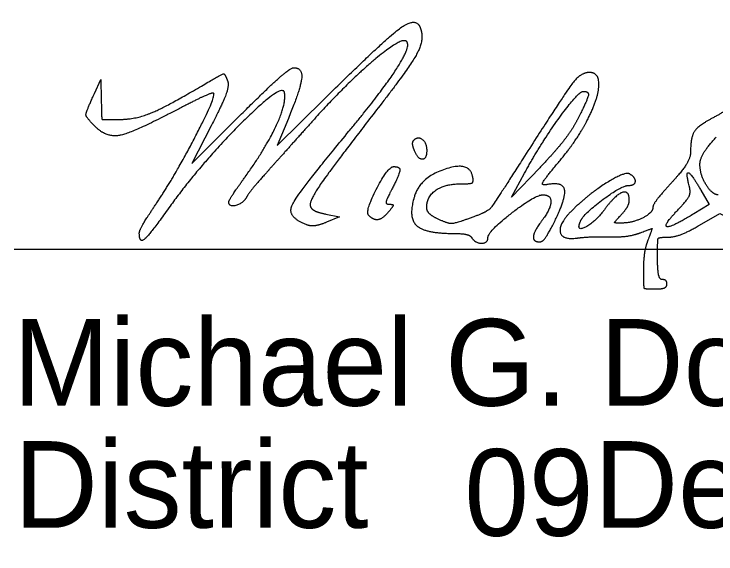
# Model space of a CAD drawing. Extents: x 0 to 40.2, y 0 to 22.
# Drawn here: x 24.5 to 25.632, y 8.324 to 9.196 of the extents above; entities that cross this region are included whole.
import ezdxf

# ---------------------------------------------------------------- set-up
doc = ezdxf.new("R2010")
doc.units = 0
doc.layers.add('SH_Data', color=7, linetype='Continuous')
doc.layers.add('SH_Text', color=7, linetype='Continuous')

msp = doc.modelspace()

# ---------------------------------------------------------------- linework, layer by layer
at = {"layer": 'SH_Data'}
msp.add_line((24.5, 8.816), (28, 8.816), dxfattribs=at)
at = {"layer": 'SH_Text'}
for p, q in [((25.1455, 8.9761), (25.1455, 8.9761)), ((25.0723, 8.8703), (25.0723, 8.8703)), ((24.7021, 8.842), (24.7021, 8.842))]:
    msp.add_line(p, q, dxfattribs=at)
for points in [[(24.6296, 9.067), (24.6401, 9.0898), (24.6407, 9.0575)], [(24.9425, 9.0269), (24.9245, 8.9834), (25.0015, 9.0594)], [(24.818, 9.015), (24.7867, 8.9543), (24.8642, 9.0315)], [(25.3481, 8.9474), (25.3027, 8.8998), (25.3235, 8.9384)], [(25.6082, 8.9109), (25.6213, 8.8879), (25.5968, 8.873)], [(25.0029, 8.8725), (25.0251, 8.868), (25.0043, 8.8594)], [(25.6056, 8.8544), (25.6388, 8.8734), (25.6847, 8.8505)]]:
    msp.add_lwpolyline(points, dxfattribs=at)
for points in [[(25.7902, 9.1956), (25.7938, 9.1838), (25.6607, 9.0449), (25.6314, 9.03)], [(25.0015, 9.0594), (25.0959, 9.1527), (25.1484, 9.1916), (25.1553, 9.1735)], [(25.1553, 9.1735), (25.1622, 9.1555), (25.1402, 9.1122), (25.0934, 9.0518)], [(25.1333, 9.1513), (25.1255, 9.1591), (25.0346, 9.082), (24.9821, 9.0233)], [(25.0402, 9.0062), (25.0944, 9.0716), (25.1407, 9.1439), (25.1333, 9.1513)], [(24.8642, 9.0315), (24.9069, 9.074), (24.946, 9.1088), (24.9511, 9.1088)], [(24.9511, 9.1088), (24.9658, 9.1088), (24.9622, 9.0746), (24.9425, 9.0269)], [(24.8022, 9.0792), (24.8352, 9.0986), (24.84, 9.0996), (24.8443, 9.0883)], [(25.4283, 9.1012), (25.4143, 9.1012), (25.3884, 9.0676), (25.3207, 8.9615)], [(25.4233, 9.0213), (25.4421, 9.0569), (25.4448, 9.1012), (25.4283, 9.1012)], [(24.8443, 9.0883), (24.8473, 9.0806), (24.8369, 9.0517), (24.818, 9.015)], [(24.6669, 9.0252), (24.6948, 9.0252), (24.7439, 9.0448), (24.8022, 9.0792)], [(24.9363, 9.0688), (24.933, 9.0855), (24.7994, 8.9521), (24.7499, 8.8827)], [(25.3235, 8.9384), (25.3479, 8.9838), (25.4102, 9.0706), (25.4184, 9.0707)], [(25.4184, 9.0707), (25.4279, 9.0708), (25.4249, 9.0565), (25.4088, 9.025)], [(24.6312, 9.0136), (24.6161, 9.0287), (24.6158, 9.0368), (24.6296, 9.067)], [(24.7295, 8.8895), (24.7593, 8.9337), (24.8264, 9.063), (24.8218, 9.0676)], [(24.8218, 9.0676), (24.8203, 9.0691), (24.7934, 9.0569), (24.7621, 9.0405)], [(24.873, 8.9328), (24.9059, 8.9786), (24.9397, 9.0512), (24.9363, 9.0688)], [(24.6407, 9.0575), (24.6413, 9.026), (24.6419, 9.0252), (24.6669, 9.0252)], [(25.0934, 9.0518), (25.0157, 8.9514), (24.9754, 8.8931), (24.9781, 8.8851)], [(24.7621, 9.0405), (24.6928, 9.0042), (24.6495, 8.9953), (24.6312, 9.0136)], [(25.4088, 9.025), (25.4004, 9.0085), (25.373, 8.9735), (25.3481, 8.9474)], [(25.6314, 9.03), (25.6047, 9.0163), (25.5913, 8.997), (25.5913, 8.9723)], [(24.9821, 9.0233), (24.9514, 8.989), (24.916, 8.9494), (24.9035, 8.9354)], [(25.3768, 8.9543), (25.3936, 8.9745), (25.4145, 9.0046), (25.4233, 9.0213)], [(24.9725, 8.855), (24.9398, 8.8675), (24.9569, 8.9056), (25.0402, 9.0062)], [(25.1455, 8.9761), (25.143, 8.9826), (25.1429, 8.9897), (25.1452, 8.9921)], [(25.1452, 8.9921), (25.1519, 8.9987), (25.1657, 8.9874), (25.1657, 8.9753)], [(25.6065, 8.9528), (25.6065, 8.9613), (25.6183, 8.981), (25.6327, 8.9967)], [(25.1657, 8.9753), (25.1657, 8.9608), (25.1512, 8.9613), (25.1455, 8.9761)], [(25.5913, 8.9723), (25.5913, 8.9636), (25.5776, 8.9416), (25.5609, 8.9235)], [(25.3207, 8.9615), (25.2731, 8.8869), (25.2631, 8.8757), (25.2358, 8.866)], [(25.0723, 8.8703), (25.066, 8.8766), (25.1031, 8.9492), (25.1126, 8.9492)], [(25.1126, 8.9492), (25.1232, 8.9492), (25.1219, 8.9367), (25.1085, 8.9108)], [(25.2398, 8.9334), (25.2347, 8.9583), (25.1556, 8.9318), (25.1462, 8.9019)], [(25.3595, 8.9201), (25.3503, 8.9184), (25.3556, 8.9289), (25.3768, 8.9543)], [(25.6361, 8.9036), (25.6262, 8.9036), (25.6065, 8.9364), (25.6065, 8.9528)], [(24.9035, 8.9354), (24.8909, 8.9213), (24.878, 8.905), (24.8746, 8.8991)], [(25.4936, 8.9371), (25.4862, 8.9417), (25.4291, 8.9064), (25.4028, 8.8811)], [(25.4913, 8.9188), (25.5015, 8.9188), (25.5031, 8.9312), (25.4936, 8.9371)], [(25.5892, 8.9183), (25.5832, 8.9412), (25.5931, 8.9373), (25.6082, 8.9109)], [(24.8465, 8.8922), (24.8465, 8.8942), (24.8584, 8.9126), (24.873, 8.9328)], [(25.2193, 8.9213), (25.2363, 8.9213), (25.2417, 8.9245), (25.2398, 8.9334)], [(25.5609, 8.9235), (25.5442, 8.9053), (25.5305, 8.8871), (25.5305, 8.8831)], [(25.1657, 8.8832), (25.1657, 8.9006), (25.1949, 8.9213), (25.2193, 8.9213)], [(25.3727, 8.8621), (25.3909, 8.8997), (25.3852, 8.9249), (25.3595, 8.9201)], [(25.4136, 8.8607), (25.4184, 8.8725), (25.4804, 8.9188), (25.4913, 8.9188)], [(25.5719, 8.8803), (25.5863, 8.8955), (25.592, 8.9078), (25.5892, 8.9183)], [(25.1085, 8.9108), (25.1006, 8.8956), (25.0997, 8.8884), (25.1056, 8.8884)], [(25.1462, 8.9019), (25.1353, 8.8678), (25.1625, 8.8413), (25.2084, 8.8413)], [(25.2645, 8.8345), (25.2645, 8.8444), (25.3403, 8.9036), (25.3529, 8.9036)], [(25.3529, 8.9036), (25.3665, 8.9036), (25.3658, 8.8809), (25.3516, 8.8622)], [(25.4925, 8.8947), (25.4925, 8.9113), (25.4702, 8.9037), (25.4538, 8.8814)], [(24.7021, 8.842), (24.7021, 8.8458), (24.7144, 8.8672), (24.7295, 8.8895)], [(24.8746, 8.8991), (24.869, 8.8892), (24.8465, 8.8836), (24.8465, 8.8922)], [(25.4799, 8.8719), (25.4868, 8.8795), (25.4925, 8.8898), (25.4925, 8.8947)], [(24.7499, 8.8827), (24.7187, 8.839), (24.7021, 8.8249), (24.7021, 8.842)], [(24.9781, 8.8851), (24.9795, 8.8806), (24.9907, 8.875), (25.0029, 8.8725)], [(25.1056, 8.8884), (25.1119, 8.8884), (25.1117, 8.8851), (25.1049, 8.877)], [(25.1852, 8.8639), (25.1745, 8.8688), (25.1657, 8.8775), (25.1657, 8.8832)], [(25.4028, 8.8811), (25.3791, 8.8583), (25.3827, 8.8304), (25.4089, 8.8339)], [(25.4538, 8.8814), (25.4376, 8.8595), (25.4065, 8.8435), (25.4136, 8.8607)], [(25.5305, 8.8831), (25.5305, 8.8744), (25.4972, 8.858), (25.4796, 8.858)], [(25.5968, 8.873), (25.5596, 8.8503), (25.5467, 8.8541), (25.5719, 8.8803)], [(25.1049, 8.877), (25.0951, 8.8651), (25.0805, 8.8621), (25.0723, 8.8703)], [(25.4796, 8.858), (25.4685, 8.858), (25.4685, 8.8593), (25.4799, 8.8719)], [(25.0043, 8.8594), (24.9928, 8.8547), (24.9785, 8.8527), (24.9725, 8.855)], [(25.2358, 8.866), (25.2113, 8.8573), (25.2007, 8.8569), (25.1852, 8.8639)], [(25.3516, 8.8622), (25.3388, 8.8452), (25.337, 8.8276), (25.3482, 8.8276)], [(25.3482, 8.8276), (25.3524, 8.8276), (25.3634, 8.8431), (25.3727, 8.8621)], [(25.5106, 8.8425), (25.5289, 8.8494), (25.5295, 8.8488), (25.5226, 8.8306)], [(25.5552, 8.8353), (25.5646, 8.8353), (25.5873, 8.8439), (25.6056, 8.8544)], [(25.2084, 8.8413), (25.2226, 8.8413), (25.236, 8.8382), (25.2384, 8.8344)], [(25.2384, 8.8344), (25.2439, 8.8255), (25.2645, 8.8256), (25.2645, 8.8345)], [(25.4089, 8.8339), (25.4193, 8.8353), (25.4422, 8.8361), (25.4596, 8.8358)], [(25.4596, 8.8358), (25.4771, 8.8354), (25.5, 8.8384), (25.5106, 8.8425)], [(25.5381, 8.801), (25.5381, 8.8314), (25.54, 8.8352), (25.5552, 8.8353)], [(25.5226, 8.8306), (25.5186, 8.82), (25.5153, 8.7979), (25.5153, 8.7815)], [(25.5457, 8.7668), (25.5415, 8.7668), (25.5381, 8.7822), (25.5381, 8.801)], [(25.5153, 8.7815), (25.5153, 8.7547), (25.5172, 8.7516), (25.5343, 8.7516)], [(25.5533, 8.7592), (25.5533, 8.7634), (25.5499, 8.7668), (25.5457, 8.7668)], [(25.5343, 8.7516), (25.5447, 8.7516), (25.5533, 8.755), (25.5533, 8.7592)]]:
    msp.add_open_spline(points, degree=2, dxfattribs=at)

# ---------------------------------------------------------------- texts
for s, p in [('Michael G. Dombrowski', (24.4983, 8.5631)), ('District       Deputy Director', (24.5, 8.366)), ('              09', (24.4983, 8.3531))]:
    msp.add_text(s, height=0.14, dxfattribs=at).set_placement(p)

doc.saveas('drawing.dxf')
